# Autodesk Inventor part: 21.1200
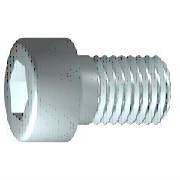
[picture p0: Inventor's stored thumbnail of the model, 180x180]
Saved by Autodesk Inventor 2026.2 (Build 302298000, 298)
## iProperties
Created: 2006-02
Part Number: 21.1200
Material: Steel, Mild
Description: M8 x 16 SHCS
Document SubType Name: Modeling
Standard: DIN 7984
Designer: Andy Moles
Standards Organization: DIN
Language: en-US
Size Designation: M8 x 16
Categories: <MemberInstance><Categories><Category DisplayName="Fasteners" InternalName="e4da775c-781d-43d5-af7c-5136215cf5a6" Mnemonic="FSTN"><Category DisplayName="Bolts"
Density: 7.85 g/cm^3
Mass: 10.6691 g
Surface Area: 9.17139 cm^2
Volume: 1.35912 cm^3
Vendor: S
Appearance: Zinc
Author: Andy Moles
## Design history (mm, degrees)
body "Solid1"
workplane "Work Plane1"
revolve "Body" stored, may be unused: angle "d10" = 90 deg
sketch "Sketch2"
  geometry: L1 (0, -9.1)-(0, 9.1) reference; L2 (-9.1, 0)-(9.1, 0) reference; L3 (2.887, 0)-(1.443, -2.5); L4 (1.443, -2.5)-(-1.443, -2.5); L5 (-1.443, -2.5)-(-2.887, 0); L6 (-2.887, 0)-(-1.443, 2.5); L7 (-1.443, 2.5)-(1.443, 2.5); L8 (1.443, 2.5)-(2.887, 0); 2 further points
  constraints: 12 end point, 1 coincident, 1 horizontal alignment, 1 point on line, 12 other
extrude "Slot" join sketch "Sketch2" stored distance "d11" = 10; taper "d12" = 0 deg
fillet "Fillet1" dims "d17" = 0.8 (= RR)
feature "Thread" dims "d13" = 16, "d14" = 0
chamfer "Chamfer1" distance "d15" = 0.76681 (= -0.5 x SPD + 0.5 x GD); stored, may be unused: second distance "d16" = 0.76681 (= GUL), angle "d27" = 45 deg
sketch "Sketch1"
  geometry: L1 (0.467, 0)-(16, 0); L2 (16, 0)-(16, 4); L3 (16, 4)-(3.75, 4); L4 (3.75, 4)-(2.983, 4); L5 (2.983, 4)-(0, 4); L6 (0, 4)-(0, 6.5); L7 (0, 6.5)-(-5, 6.5); L8 (-5, 6.5)-(-5, 2.887); L9 (-5, 2.887)-(-1.2, 2.887); L10 (-1.2, 2.887)-(0.467, 0); L11 (-9.2, 0)-(20.2, 0) reference; L12 (0, -1.3)-(0, 7.8) reference; L13 (3.75, 4)-(0, 4)
  constraints: 22 end point, 6 parallel, 2 collinear, 2 perpendicular, 1 horizontal, 1 point on line
  dimensions: "d1" = 12.25 distance from line of L3.end L2 (= GEL); "d2" = 0.76691 distance of L4.end L3.end (computed from GAL); "d3" = 5 distance between parallel lines of L8 L6 (= KOH); "d4" = 3.8 distance of L8.end L9.end (= INTI); "d5" = 60 deg angle of L10 L1; "d6" = 8 diameter of L3 L1 (= GD); "d7" = 8 diameter of L5 L1 (= BDM); "d8" = 5.7735 diameter of L9 L1 (= 1.1547 x SW); "d9" = 13 diameter of L7 L1 (= KOD); "d26" = 16 distance between parallel lines of L12 L2 (= NLG)
other parameters: "GD" = 8 (= NND) [user parameter; used in 2 equation terms], "NLG" = 16 [user parameter; used in 1 equation term], "GEL" = 12.25 [user parameter; used in 1 equation term], "KOD" = 13 [user parameter; used in 1 equation term], "KOH" = 5 [user parameter; used in 1 equation term], "INTI" = 3.8 [user parameter; used in 1 equation term], "GAL" = 0.76681 (= 0.61345 x PTC) [user parameter; used in 1 equation term], "GUL" = 0.76681 (= 0.61345 x PTC) [user parameter; used in 1 equation term], "BDM" = 8 (= NND) [user parameter; used in 1 equation term], "SW" = 5 [user parameter; used in 2 equation terms], "RR" = 0.8 [user parameter; used in 1 equation term], "SPD" = 6.46637 (= NND - 1.2269 x PTC) [user parameter; used in 1 equation term], "d19" = 0, "d28" = 0, "d29" = 0, "TOA" = 30 deg [user parameter], "GD1" = 6.46637 (= THREADDIA - 1.2269 x PTC) [user parameter], "THREADDIA" = 8 [user parameter; used in 1 equation term], "FAWI" = 45 deg [user parameter], "ANG" = 120 deg [user parameter], "TPU" = 8 (computed from PTC) [user parameter], "PTC" = 1.25 [user parameter; used in 5 equation terms], "NND" = 8 [user parameter; used in 3 equation terms], "E0" = 5.775 (= 1.155 x SW) [user parameter]
